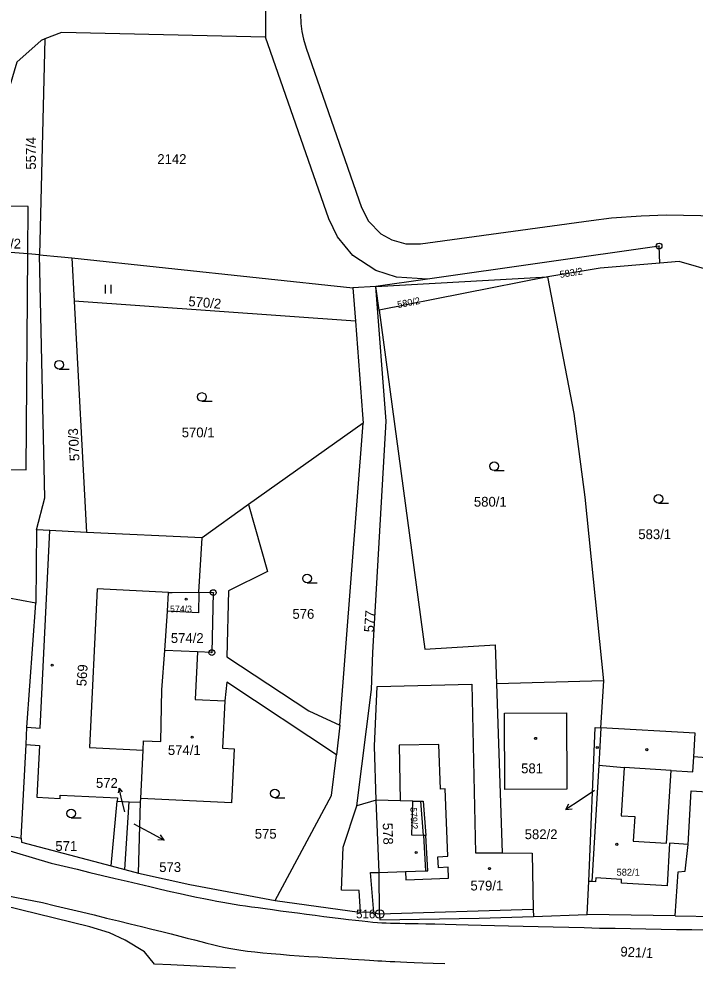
# Model space of a CAD drawing. Extents: x -504988 to -494607, y -1123820 to -1114018.
# Drawn here: x -499475.3 to -499357.9, y -1121459.6 to -1121295.8 of the extents above; entities that cross this region are included whole.
import ezdxf

# ---------------------------------------------------------------- set-up
doc = ezdxf.new("R2010")
doc.units = 0
for name, color, linetype in [('Hranice parcel', 7, 'Continuous'), ('Parcelní čísla', 7, 'Continuous'), ('Pop  PČ popisy', 7, 'Continuous'), ('Vnitřní kresba', 7, 'Continuous'), ('Značky bodu BP', 7, 'Continuous'), ('Značky budov', 7, 'Continuous'), ('Značky kultur', 7, 'Continuous')]:
    doc.layers.add(name, color=color, linetype=linetype)

msp = doc.modelspace()

# ---------------------------------------------------------------- linework, layer by layer
at = {"layer": 'Hranice parcel'}
for p, q in [((-499432.49, -1121293.4), (-499432.46, -1121298.95)), ((-499470.76, -1121299.24), (-499471.73, -1121336.7)), ((-499473.74, -1121336.51), (-499480.88, -1121335.99)), ((-499471.73, -1121336.7), (-499473.74, -1121336.51)), ((-499466.08, -1121337.24), (-499417.32, -1121342.43)), ((-499466.08, -1121337.24), (-499465.68, -1121344.72)), ((-499413.32, -1121342.21), (-499383.45, -1121340.53)), ((-499404.35, -1121340.93), (-499413.32, -1121342.21)), ((-499383.45, -1121340.53), (-499412.77, -1121346.3)), ((-499413.32, -1121342.21), (-499417.32, -1121342.43)), ((-499417.32, -1121342.43), (-499416.88, -1121348.21)), ((-499412.77, -1121346.3), (-499413.32, -1121342.21)), ((-499416.88, -1121348.21), (-499465.68, -1121344.72)), ((-499465.68, -1121344.72), (-499463.57, -1121384.87)), ((-499415.51, -1121365.89), (-499435.43, -1121380.04)), ((-499419.58, -1121418.33), (-499415.51, -1121365.89)), ((-499435.43, -1121380.04), (-499443.48, -1121385.83)), ((-499472.22, -1121384.45), (-499472.35, -1121397.15)), ((-499443.48, -1121385.83), (-499463.57, -1121384.87)), ((-499444.05, -1121395.27), (-499443.48, -1121385.83)), ((-499449.98, -1121405.35), (-499449.52, -1121398.55)), ((-499373.77, -1121410.65), (-499392.38, -1121411.15)), ((-499374.24, -1121418.79), (-499373.77, -1121410.65)), ((-499419.58, -1121418.33), (-499420.18, -1121423.47)), ((-499474.87, -1121437.96), (-499474.03, -1121421.7)), ((-499459.28, -1121442.76), (-499458.21, -1121431.51)), ((-499458.21, -1121431.51), (-499456.15, -1121431.61)), ((-499456.88, -1121443.4), (-499456.15, -1121431.61)), ((-499456.15, -1121431.61), (-499454.16, -1121431.7)), ((-499454.52, -1121444.02), (-499454.16, -1121431.7)), ((-499454.16, -1121431.7), (-499454.12, -1121431.04)), ((-499406.91, -1121431.49), (-499405.5, -1121431.52)), ((-499405.5, -1121431.52), (-499405.1, -1121431.53)), ((-499405.1, -1121431.53), (-499404.66, -1121437.5)), ((-499459.28, -1121442.76), (-499456.88, -1121443.4)), ((-499456.88, -1121443.4), (-499454.52, -1121444.02)), ((-499376.63, -1121451.16), (-499376.35, -1121445.45)), ((-499375.8, -1121445.48), (-499376.35, -1121445.45)), ((-499413.7, -1121450.83), (-499415.97, -1121450.78)), ((-499385.98, -1121451.51), (-499376.63, -1121451.16)), ((-499361.36, -1121451.43), (-499376.63, -1121451.16)), ((-499361.36, -1121451.43), (-499349.31, -1121451.65))]:
    msp.add_line(p, q, dxfattribs=at)
for points in [[(-499426.38, -1121294.95), (-499426.34, -1121296.55), (-499426.17, -1121297.95), (-499425.91, -1121299.28), (-499425.44, -1121300.86), (-499415.82, -1121328.48), (-499414.62, -1121330.83), (-499412.44, -1121333.04), (-499410.53, -1121334.11), (-499408.1, -1121334.77), (-499405.57, -1121334.77), (-499375.94, -1121330.72), (-499372.41, -1121330.3), (-499367.27, -1121329.91), (-499362.9, -1121329.78), (-499356.92, -1121329.9), (-499352.59, -1121330.21), (-499326.57, -1121332.59)], [(-499470.76, -1121299.24), (-499471.45, -1121299.51), (-499475.66, -1121303.26), (-499480.87, -1121320.65), (-499480.83, -1121328.26)], [(-499432.46, -1121298.95), (-499467.9, -1121298.1), (-499470.76, -1121299.24)], [(-499404.35, -1121340.93), (-499409.72, -1121340.59), (-499413.34, -1121339.44), (-499417.31, -1121336.79), (-499419.99, -1121333.59), (-499421.49, -1121330.45), (-499432.46, -1121298.95)], [(-499473.74, -1121336.51), (-499473.68, -1121328.31), (-499480.83, -1121328.26)], [(-499364.03, -1121338.12), (-499364.16, -1121335.17), (-499404.35, -1121340.93)], [(-499486.99, -1121343.91), (-499487.21, -1121373.91), (-499474.01, -1121374.01), (-499473.74, -1121336.51)], [(-499472.22, -1121384.45), (-499470.77, -1121378.85), (-499471.73, -1121336.7)], [(-499471.73, -1121336.7), (-499467.94, -1121337.04), (-499466.08, -1121337.24)], [(-499364.03, -1121338.12), (-499374.37, -1121338.99), (-499383.45, -1121340.53)], [(-499354.23, -1121339.73), (-499360.67, -1121337.84), (-499364.03, -1121338.12)], [(-499373.77, -1121410.65), (-499376.97, -1121378.77), (-499378.91, -1121364.24), (-499383.45, -1121340.53)], [(-499416.65, -1121432.32), (-499414.08, -1121412.14), (-499413.87, -1121405.7), (-499411.52, -1121365.58), (-499413.32, -1121342.21)], [(-499412.77, -1121346.3), (-499404.82, -1121405.14), (-499392.61, -1121404.37), (-499392.38, -1121411.15)], [(-499416.88, -1121348.21), (-499415.63, -1121364.4), (-499415.51, -1121365.89)], [(-499435.43, -1121380.04), (-499432.11, -1121391.65), (-499438.9, -1121395.03), (-499439.2, -1121406.49), (-499424.94, -1121415.84), (-499419.58, -1121418.33)], [(-499463.57, -1121384.87), (-499469.93, -1121384.56), (-499472.22, -1121384.45)], [(-499472.35, -1121397.15), (-499482.38, -1121395.33), (-499482.87, -1121397.56), (-499485.69, -1121433.28), (-499483.21, -1121435.9)], [(-499444.05, -1121395.27), (-499441.55, -1121395.32), (-499441.8, -1121405.73), (-499444.3, -1121405.62), (-499449.98, -1121405.35)], [(-499449.52, -1121398.55), (-499449.3, -1121395.28), (-499448.7, -1121395.31), (-499444.05, -1121395.27)], [(-499444.05, -1121395.27), (-499444.1, -1121398.82), (-499449.52, -1121398.55)], [(-499474.03, -1121421.7), (-499473.9, -1121418.67), (-499472.35, -1121397.15)], [(-499454.12, -1121431.04), (-499453.74, -1121422.64), (-499453.66, -1121421.04), (-499450.64, -1121421.19), (-499450.45, -1121412.22), (-499449.98, -1121405.35)], [(-499420.18, -1121423.47), (-499439.18, -1121410.87), (-499439.54, -1121414.12), (-499439.94, -1121422.34), (-499437.91, -1121422.43), (-499438.36, -1121431.8), (-499454.12, -1121431.04)], [(-499392.38, -1121411.15), (-499391.38, -1121440.5), (-499386.2, -1121440.52), (-499386, -1121450.31), (-499385.98, -1121451.51)], [(-499376.35, -1121445.45), (-499375.24, -1121418.73), (-499374.24, -1121418.79)], [(-499374.24, -1121418.79), (-499374.62, -1121425.27), (-499375.8, -1121445.48)], [(-499349.56, -1121424.41), (-499354.55, -1121424.12), (-499358.12, -1121423.8), (-499357.89, -1121419.74), (-499374.24, -1121418.79)], [(-499474.03, -1121421.7), (-499471.72, -1121421.87), (-499472.16, -1121430.84), (-499468.13, -1121431.03), (-499468.11, -1121430.46), (-499458.18, -1121430.94), (-499458.21, -1121431.51)], [(-499430.82, -1121448.77), (-499421, -1121430.55), (-499420.18, -1121423.47)], [(-499361.36, -1121451.43), (-499360.83, -1121443.79), (-499359.6, -1121443.68), (-499359.11, -1121439.02), (-499358.57, -1121429.72), (-499354.89, -1121429.93), (-499354.77, -1121427.9), (-499349.78, -1121428.19)], [(-499406.91, -1121431.49), (-499409.12, -1121431.44), (-499413.28, -1121431.33), (-499416.65, -1121432.32)], [(-499404.66, -1121437.5), (-499405.06, -1121437.49), (-499407.06, -1121437.44), (-499406.91, -1121431.49)], [(-499415.97, -1121450.78), (-499416.21, -1121447.05), (-499419.3, -1121446.95), (-499419.02, -1121439.5), (-499416.65, -1121432.32)], [(-499483.21, -1121435.9), (-499479.01, -1121437.13), (-499474.87, -1121437.96)], [(-499474.87, -1121437.96), (-499474.86, -1121438.64), (-499459.28, -1121442.76)], [(-499413.7, -1121450.83), (-499414.24, -1121443.92), (-499412.74, -1121443.9), (-499408.18, -1121443.75), (-499404.68, -1121443.61), (-499404.27, -1121443.6), (-499404.66, -1121437.5)], [(-499454.52, -1121444.02), (-499445.62, -1121445.99), (-499430.82, -1121448.77)], [(-499437.7, -1121460.51), (-499448.91, -1121459.94), (-499451.77, -1121459.81), (-499453.49, -1121457.69), (-499456.84, -1121455.67), (-499459.58, -1121454.36), (-499462.95, -1121453.35), (-499481.22, -1121448.86)], [(-499430.82, -1121448.77), (-499416.18, -1121450.78), (-499415.97, -1121450.78)], [(-499413.7, -1121450.83), (-499412.66, -1121451.1), (-499412.65, -1121452.1), (-499395.38, -1121451.85), (-499385.98, -1121451.51)]]:
    msp.add_lwpolyline(points, dxfattribs=at)
at = {"layer": 'Pop  PČ popisy'}
for p, q in [((-499457.87, -1121429.29), (-499458.06, -1121430.05)), ((-499457.4, -1121431.34), (-499457.87, -1121429.29)), ((-499457.87, -1121429.29), (-499457.37, -1121429.9)), ((-499375.35, -1121429.67), (-499377.85, -1121431.32)), ((-499456.92, -1121433.39), (-499457.4, -1121431.34)), ((-499377.85, -1121431.32), (-499380.37, -1121432.95)), ((-499380.37, -1121432.95), (-499379.8, -1121431.99)), ((-499380.37, -1121432.95), (-499379.25, -1121432.83)), ((-499455.36, -1121435.44), (-499452.71, -1121436.86)), ((-499452.71, -1121436.86), (-499450.06, -1121438.27)), ((-499450.06, -1121438.27), (-499451.18, -1121438.24)), ((-499450.06, -1121438.27), (-499450.71, -1121437.36))]:
    msp.add_line(p, q, dxfattribs=at)
at = {"layer": 'Vnitřní kresba'}
for p, q in [((-499471.58, -1121418.84), (-499469.93, -1121384.56)), ((-499461.7, -1121394.68), (-499463.03, -1121422.19)), ((-499449.3, -1121395.28), (-499461.7, -1121394.68)), ((-499444.3, -1121405.62), (-499444.7, -1121413.87)), ((-499413.58, -1121421.98), (-499413.11, -1121411.6)), ((-499413.11, -1121411.6), (-499396.68, -1121411.24)), ((-499396.68, -1121411.24), (-499396.04, -1121440.49)), ((-499444.7, -1121413.87), (-499439.54, -1121414.12)), ((-499390.97, -1121416.22), (-499380.23, -1121416.17)), ((-499390.92, -1121429.47), (-499390.97, -1121416.22)), ((-499380.23, -1121416.17), (-499380.17, -1121429.42)), ((-499473.9, -1121418.67), (-499471.58, -1121418.84)), ((-499463.03, -1121422.19), (-499453.74, -1121422.64)), ((-499413.28, -1121431.33), (-499413.58, -1121421.98)), ((-499402.4, -1121421.67), (-499409.26, -1121421.77)), ((-499409.26, -1121421.77), (-499409.12, -1121431.44)), ((-499402.1, -1121429.43), (-499402.4, -1121421.67)), ((-499358.28, -1121426.45), (-499358.12, -1121423.8)), ((-499374.62, -1121425.27), (-499370.19, -1121425.67)), ((-499370.19, -1121425.67), (-499370.71, -1121434.04)), ((-499362.06, -1121426.18), (-499370.19, -1121425.67)), ((-499362.86, -1121438.81), (-499362.06, -1121426.18)), ((-499362.06, -1121426.18), (-499358.28, -1121426.45)), ((-499401.28, -1121429.4), (-499402.1, -1121429.43)), ((-499400.84, -1121441.09), (-499401.28, -1121429.4)), ((-499380.17, -1121429.42), (-499390.92, -1121429.47)), ((-499412.74, -1121443.9), (-499413.28, -1121431.33)), ((-499405.06, -1121437.49), (-499405.5, -1121431.52)), ((-499370.71, -1121434.04), (-499368.38, -1121434.18)), ((-499368.38, -1121434.18), (-499368.65, -1121438.44)), ((-499484.7, -1121437.82), (-499469.69, -1121442.26)), ((-499405.06, -1121437.49), (-499404.68, -1121443.61)), ((-499368.65, -1121438.44), (-499362.86, -1121438.81)), ((-499362.32, -1121438.83), (-499362.75, -1121446.24)), ((-499359.11, -1121439.02), (-499362.32, -1121438.83)), ((-499402.54, -1121441.16), (-499400.84, -1121441.09)), ((-499402.46, -1121443.06), (-499402.54, -1121441.16)), ((-499396.04, -1121440.49), (-499391.38, -1121440.5)), ((-499400.76, -1121442.99), (-499402.46, -1121443.06)), ((-499400.69, -1121444.89), (-499400.76, -1121442.99)), ((-499412.66, -1121451.1), (-499412.74, -1121443.9)), ((-499408.18, -1121443.75), (-499408.13, -1121445.18)), ((-499408.13, -1121445.18), (-499400.69, -1121444.89)), ((-499375.14, -1121444.85), (-499375.18, -1121445.52)), ((-499370.66, -1121445.12), (-499375.14, -1121444.85)), ((-499370.7, -1121445.77), (-499370.66, -1121445.12)), ((-499486, -1121446.23), (-499471.21, -1121449.11)), ((-499375.18, -1121445.52), (-499375.8, -1121445.48)), ((-499362.75, -1121446.24), (-499370.7, -1121445.77)), ((-499386, -1121450.31), (-499412.66, -1121451.1))]:
    msp.add_line(p, q, dxfattribs=at)
for points in [[(-499469.69, -1121442.26), (-499467.44, -1121442.8), (-499465.17, -1121443.34), (-499462.95, -1121443.88), (-499460.76, -1121444.4), (-499458.6, -1121444.91), (-499456.51, -1121445.41), (-499454.5, -1121445.88), (-499452.54, -1121446.34), (-499450.7, -1121446.77), (-499448.96, -1121447.17), (-499447.31, -1121447.54), (-499445.81, -1121447.87), (-499444.44, -1121448.17), (-499443.17, -1121448.43), (-499442.02, -1121448.66), (-499440.93, -1121448.87), (-499439.9, -1121449.06), (-499438.91, -1121449.23), (-499437.93, -1121449.39), (-499436.94, -1121449.54), (-499435.94, -1121449.69), (-499434.89, -1121449.84), (-499433.76, -1121450), (-499432.56, -1121450.16), (-499431.26, -1121450.34), (-499429.86, -1121450.53), (-499428.41, -1121450.72), (-499426.91, -1121450.92), (-499425.37, -1121451.12), (-499423.85, -1121451.32), (-499422.34, -1121451.51), (-499420.85, -1121451.7), (-499419.43, -1121451.88), (-499418.09, -1121452.04), (-499416.84, -1121452.19), (-499415.71, -1121452.31), (-499414.71, -1121452.41), (-499413.82, -1121452.5), (-499413.01, -1121452.56), (-499412.26, -1121452.61), (-499411.52, -1121452.65), (-499410.78, -1121452.67), (-499410.01, -1121452.69), (-499409.17, -1121452.71), (-499408.25, -1121452.72), (-499407.21, -1121452.74), (-499406, -1121452.76), (-499404.63, -1121452.78), (-499403.06, -1121452.81), (-499401.29, -1121452.85), (-499399.36, -1121452.9), (-499397.29, -1121452.96), (-499395.05, -1121453.02), (-499392.71, -1121453.08), (-499390.28, -1121453.14), (-499387.74, -1121453.21), (-499385.16, -1121453.28), (-499382.53, -1121453.34), (-499379.83, -1121453.41), (-499377.16, -1121453.47), (-499374.49, -1121453.53), (-499371.79, -1121453.58), (-499369.12, -1121453.63), (-499366.46, -1121453.68), (-499363.77, -1121453.72), (-499361.12, -1121453.77), (-499358.46, -1121453.81), (-499355.78, -1121453.85)], [(-499471.21, -1121449.11), (-499468.95, -1121449.66), (-499466.67, -1121450.2), (-499464.44, -1121450.74), (-499462.24, -1121451.27), (-499460.07, -1121451.8), (-499457.99, -1121452.3), (-499455.98, -1121452.79), (-499454.03, -1121453.27), (-499452.2, -1121453.73), (-499450.47, -1121454.16), (-499448.85, -1121454.56), (-499447.38, -1121454.94), (-499446.05, -1121455.29), (-499444.82, -1121455.61), (-499443.71, -1121455.9), (-499442.68, -1121456.16), (-499441.68, -1121456.41), (-499440.73, -1121456.63), (-499439.79, -1121456.84), (-499438.82, -1121457.03), (-499437.82, -1121457.21), (-499436.75, -1121457.37), (-499435.59, -1121457.53), (-499434.34, -1121457.68), (-499432.96, -1121457.82), (-499431.47, -1121457.96), (-499429.9, -1121458.09), (-499428.29, -1121458.22), (-499426.62, -1121458.34), (-499424.97, -1121458.46), (-499423.34, -1121458.56), (-499421.73, -1121458.66), (-499420.21, -1121458.76), (-499418.79, -1121458.84), (-499417.47, -1121458.92), (-499416.31, -1121458.99), (-499415.31, -1121459.05), (-499414.44, -1121459.11), (-499413.67, -1121459.16), (-499412.96, -1121459.2), (-499412.27, -1121459.24), (-499411.58, -1121459.28), (-499410.84, -1121459.32), (-499410.01, -1121459.36), (-499409.07, -1121459.4), (-499407.97, -1121459.45), (-499406.66, -1121459.5), (-499405.14, -1121459.55), (-499403.37, -1121459.61), (-499401.33, -1121459.68)]]:
    msp.add_lwpolyline(points, dxfattribs=at)
at = {"layer": 'Značky bodu BP'}
for centre, radius in [((-499364.16, -1121335.17), 0.5), ((-499364.16, -1121335.17), 0.0303), ((-499441.55, -1121395.32), 0.5), ((-499441.55, -1121395.32), 0.0303), ((-499441.8, -1121405.73), 0.5), ((-499441.8, -1121405.73), 0.0303), ((-499412.66, -1121451.1), 0.75), ((-499412.66, -1121451.1), 0.03)]:
    msp.add_circle(centre, radius, dxfattribs=at)
at = {"layer": 'Značky budov'}
for centre in [(-499446.25, -1121396.46), (-499469.5, -1121407.91), (-499445.2, -1121420.4), (-499385.58, -1121420.62), (-499374.88, -1121422.21), (-499366.26, -1121422.58), (-499406.31, -1121440.44), (-499371.5, -1121439.01), (-499393.59, -1121443.23)]:
    msp.add_circle(centre, 0.175, dxfattribs=at)
at = {"layer": 'Značky kultur'}
for p, q in [((-499460.28, -1121343.43), (-499460.28, -1121341.93)), ((-499459.28, -1121343.43), (-499459.28, -1121341.93)), ((-499468.29, -1121356.52), (-499466.54, -1121356.52)), ((-499443.51, -1121362.12), (-499441.76, -1121362.12)), ((-499392.79, -1121374.15), (-499391.04, -1121374.15)), ((-499364.25, -1121379.79), (-499362.5, -1121379.79)), ((-499425.27, -1121393.62), (-499423.52, -1121393.62)), ((-499430.85, -1121430.92), (-499429.1, -1121430.92)), ((-499466.23, -1121434.4), (-499464.48, -1121434.4))]:
    msp.add_line(p, q, dxfattribs=at)
for centre in [(-499468.29, -1121355.77), (-499443.51, -1121361.37), (-499392.79, -1121373.4), (-499364.25, -1121379.04), (-499425.27, -1121392.87), (-499430.85, -1121430.17), (-499466.23, -1121433.65)]:
    msp.add_circle(centre, 0.75, dxfattribs=at)

# ---------------------------------------------------------------- texts
at = {"layer": 'Parcelní čísla'}
for s, height, rotation, p in [('557/4', 1.7, 90, (-499472.34, -1121321.92)), ('583/2', 1.2, 9, (-499381.32, -1121340.71)), ('570/2', 1.7, 355, (-499445.92, -1121345.58)), ('580/2', 1.2, 11, (-499409.48, -1121345.96)), ('570/3', 1.7, 93, (-499464.76, -1121372.44)), ('577', 1.7, 86, (-499413.69, -1121402.26)), ('569', 1.7, 86, (-499463.6, -1121411.62)), ('579/2', 1.139, 273, (-499407.36, -1121432.61)), ('578', 1.7, 272, (-499412.14, -1121435.31)), ('921/1', 1.7, 357, (-499370.91, -1121458.45))]:
    msp.add_text(s, height=height, rotation=rotation, dxfattribs=at).set_placement(p)
for s, height, p in [('2142', 1.7, (-499451.26, -1121320.93)), ('538/2', 1.7, (-499480.61, -1121335.61)), ('570/1', 1.7, (-499447.02, -1121368.37)), ('580/1', 1.7, (-499396.3, -1121380.4)), ('583/1', 1.7, (-499367.76, -1121386.04)), ('574/3', 1.139, (-499449.06, -1121398.73)), ('576', 1.7, (-499427.8, -1121399.87)), ('574/2', 1.7, (-499448.91, -1121404.06)), ('574/1', 1.7, (-499449.42, -1121423.5)), ('581', 1.7, (-499388.1, -1121426.67)), ('572', 1.7, (-499461.91, -1121429.21)), ('575', 1.7, (-499434.34, -1121438.03)), ('582/2', 1.7, (-499387.48, -1121438.11)), ('571', 1.7, (-499468.96, -1121440.15)), ('573', 1.7, (-499450.93, -1121443.81)), ('582/1', 1.2, (-499371.53, -1121444.45)), ('579/1', 1.7, (-499396.9, -1121447.02))]:
    msp.add_text(s, height=height, dxfattribs=at).set_placement(p)
at = {"layer": 'Značky bodu BP'}
msp.add_text('516', height=1.5, dxfattribs=at).set_placement((-499416.76, -1121451.85))

doc.saveas('drawing.dxf')
